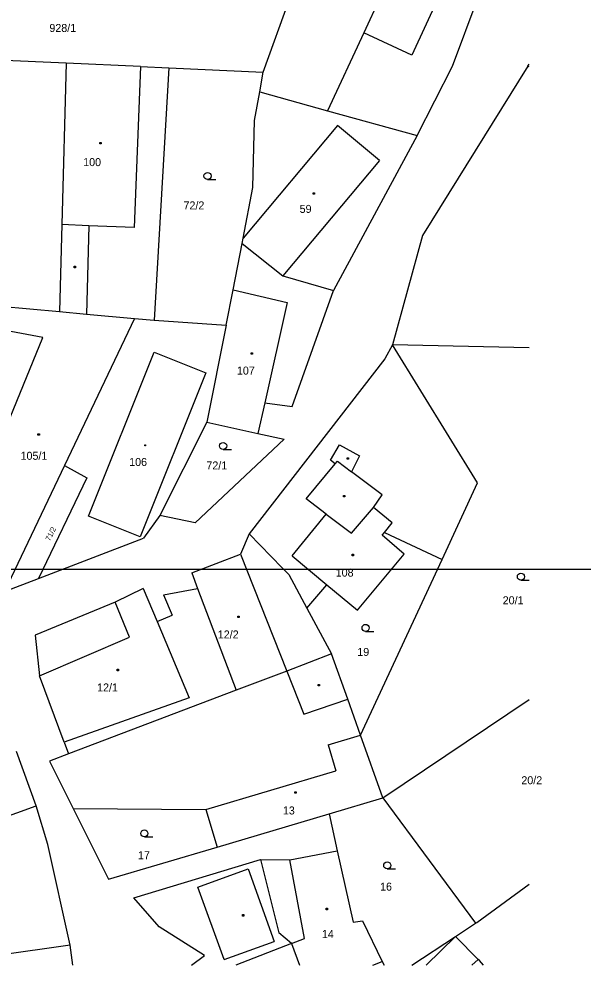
# Model space of a CAD drawing. Extents: x -770973 to -770265, y -1049936 to -1049427.
# Drawn here: x -770484.2 to -770424.3, y -1049934.8 to -1049834.2 of the extents above; entities that cross this region are included whole.
import ezdxf

# ---------------------------------------------------------------- set-up
doc = ezdxf.new("R2010")
doc.units = 0
for name, color, linetype in [('Vrstva 1', 7, 'Continuous'), ('Vrstva 14', 7, 'Continuous'), ('Vrstva 15', 7, 'Continuous'), ('Vrstva 2', 7, 'Continuous'), ('Vrstva 23', 7, 'Continuous'), ('Vrstva 25', 7, 'Continuous'), ('Vrstva 63', 7, 'Continuous')]:
    doc.layers.add(name, color=color, linetype=linetype)

msp = doc.modelspace()

# ---------------------------------------------------------------- linework, layer by layer
at = {"layer": 'Vrstva 1'}
for p, q in [((-770458.29, -1049839.9), (-770450.36, -1049817.83)), ((-770440.9, -1049821.18), (-770447.63, -1049835.71)), ((-770438.2, -1049839.27), (-770432.93, -1049825.06)), ((-770447.63, -1049835.71), (-770451.47, -1049843.99)), ((-770479.2, -1049838.96), (-770486.82, -1049838.62)), ((-770479.2, -1049838.96), (-770479.66, -1049856.1)), ((-770471.31, -1049839.31), (-770479.2, -1049838.96)), ((-770471.31, -1049839.31), (-770468.31, -1049839.45)), ((-770468.31, -1049839.45), (-770469.89, -1049866.23)), ((-770468.31, -1049839.45), (-770458.29, -1049839.9)), ((-770441.96, -1049846.64), (-770438.2, -1049839.27)), ((-770430.2, -1049839.26), (-770441.38, -1049857.25)), ((-770430.2, -1049839.26), (-770430.07, -1049839.05)), ((-770430.07, -1049839.34), (-770430.2, -1049839.26)), ((-770458.67, -1049841.99), (-770458.29, -1049839.9)), ((-770459.23, -1049845.04), (-770458.67, -1049841.99)), ((-770458.67, -1049841.99), (-770451.47, -1049843.99)), ((-770451.47, -1049843.99), (-770441.96, -1049846.64)), ((-770459.41, -1049852.14), (-770459.23, -1049845.04)), ((-770441.96, -1049846.64), (-770450.83, -1049863.11)), ((-770460.43, -1049857.53), (-770459.41, -1049852.14)), ((-770479.66, -1049856.1), (-770479.91, -1049865.34)), ((-770460.54, -1049858.09), (-770460.43, -1049857.53)), ((-770441.38, -1049857.25), (-770444.57, -1049868.85)), ((-770461.5, -1049863.01), (-770460.54, -1049858.09)), ((-770460.54, -1049858.09), (-770456.2, -1049861.52)), ((-770456.2, -1049861.52), (-770450.83, -1049863.11)), ((-770462.24, -1049866.78), (-770461.5, -1049863.01)), ((-770455.22, -1049875.43), (-770450.83, -1049863.11)), ((-770486.23, -1049864.75), (-770479.91, -1049865.34)), ((-770479.91, -1049865.34), (-770477.06, -1049865.61)), ((-770471.98, -1049866.08), (-770479.4, -1049881.69)), ((-770477.06, -1049865.61), (-770471.98, -1049866.08)), ((-770471.98, -1049866.08), (-770469.89, -1049866.23)), ((-770469.89, -1049866.23), (-770462.24, -1049866.78)), ((-770462.24, -1049866.78), (-770464.3, -1049877.09)), ((-770444.57, -1049868.85), (-770445.39, -1049870.36)), ((-770435.53, -1049883.52), (-770444.57, -1049868.85)), ((-770430.07, -1049869.18), (-770444.57, -1049868.85)), ((-770445.39, -1049870.36), (-770459.79, -1049888.94)), ((-770458.13, -1049875.04), (-770458.86, -1049878.29)), ((-770458.13, -1049875.04), (-770455.22, -1049875.43)), ((-770464.3, -1049877.09), (-770469.28, -1049887)), ((-770464.3, -1049877.09), (-770458.86, -1049878.29)), ((-770458.86, -1049878.29), (-770456.08, -1049878.9)), ((-770456.08, -1049878.9), (-770465.52, -1049887.77)), ((-770479.4, -1049881.69), (-770485.77, -1049895.07)), ((-770479.4, -1049881.69), (-770477.03, -1049882.99)), ((-770477.03, -1049882.99), (-770482.17, -1049893.68)), ((-770439.31, -1049891.66), (-770435.53, -1049883.52)), ((-770469.28, -1049887), (-770471.02, -1049889.4)), ((-770465.52, -1049887.77), (-770469.28, -1049887)), ((-770482.17, -1049893.68), (-770471.02, -1049889.4)), ((-770459.79, -1049888.94), (-770460.71, -1049891.12)), ((-770456.27, -1049892.56), (-770459.79, -1049888.94)), ((-770445.66, -1049889.1), (-770445.42, -1049888.81)), ((-770443.32, -1049891.12), (-770445.66, -1049889.1)), ((-770445.42, -1049888.81), (-770439.31, -1049891.66)), ((-770465.89, -1049893.1), (-770460.71, -1049891.12)), ((-770448.3, -1049897.07), (-770443.32, -1049891.12)), ((-770447.98, -1049910.33), (-770439.31, -1049891.66)), ((-770455.58, -1049893.28), (-770456.27, -1049892.56)), ((-770485.77, -1049895.07), (-770482.17, -1049893.68)), ((-770465.89, -1049893.1), (-770465.26, -1049894.75)), ((-770455.58, -1049893.28), (-770453.65, -1049896.86)), ((-770471.04, -1049894.75), (-770474.02, -1049896.22)), ((-770471.04, -1049894.75), (-770469.57, -1049898.26)), ((-770468.88, -1049895.42), (-770465.26, -1049894.75)), ((-770465.26, -1049894.75), (-770461.16, -1049905.56)), ((-770453.65, -1049896.86), (-770451.55, -1049894.35)), ((-770451.55, -1049894.35), (-770448.3, -1049897.07)), ((-770468.88, -1049895.42), (-770467.97, -1049897.59)), ((-770474.02, -1049896.22), (-770482.51, -1049899.71)), ((-770469.57, -1049898.26), (-770467.97, -1049897.59)), ((-770453.65, -1049896.86), (-770451.03, -1049901.71)), ((-770482.51, -1049899.71), (-770482.06, -1049904.03)), ((-770451.03, -1049901.71), (-770455.79, -1049903.52)), ((-770449.33, -1049906.52), (-770451.03, -1049901.71)), ((-770455.79, -1049903.52), (-770461.16, -1049905.56)), ((-770479.44, -1049911.09), (-770482.06, -1049904.03)), ((-770461.16, -1049905.56), (-770478.98, -1049912.33)), ((-770447.98, -1049910.33), (-770449.33, -1049906.52)), ((-770445.61, -1049917.01), (-770430.07, -1049906.54)), ((-770445.61, -1049917.01), (-770447.98, -1049910.33)), ((-770479.44, -1049911.09), (-770478.98, -1049912.33)), ((-770482.41, -1049917.84), (-770484.49, -1049912.07)), ((-770478.98, -1049912.33), (-770480.99, -1049913.1)), ((-770480.99, -1049913.1), (-770478.47, -1049918.14)), ((-770481.17, -1049921.95), (-770482.41, -1049917.84)), ((-770451.31, -1049918.7), (-770445.61, -1049917.01)), ((-770445.61, -1049917.01), (-770435.75, -1049930.32)), ((-770478.47, -1049918.14), (-770464.38, -1049918.23)), ((-770478.47, -1049918.14), (-770474.71, -1049925.65)), ((-770464.38, -1049918.23), (-770463.19, -1049922.23)), ((-770463.19, -1049922.23), (-770451.31, -1049918.7)), ((-770451.31, -1049918.7), (-770450.43, -1049922.62)), ((-770478.8, -1049932.64), (-770481.17, -1049921.95)), ((-770474.71, -1049925.65), (-770463.19, -1049922.23)), ((-770455.48, -1049923.57), (-770450.43, -1049922.62)), ((-770450.43, -1049922.62), (-770448.75, -1049930.19)), ((-770472.03, -1049927.6), (-770458.57, -1049923.56)), ((-770458.57, -1049923.56), (-770455.48, -1049923.57)), ((-770458.57, -1049923.56), (-770456.64, -1049931.32)), ((-770435.6, -1049930.22), (-770430.07, -1049926.18)), ((-770469.35, -1049930.71), (-770472.03, -1049927.6)), ((-770464.53, -1049933.76), (-770469.35, -1049930.71)), ((-770448.75, -1049930.19), (-770447.75, -1049930.05)), ((-770447.75, -1049930.05), (-770445.66, -1049934.37)), ((-770437.87, -1049931.71), (-770435.75, -1049930.32)), ((-770435.75, -1049930.32), (-770435.6, -1049930.22)), ((-770455.31, -1049932.48), (-770456.64, -1049931.32)), ((-770442.51, -1049934.76), (-770437.87, -1049931.71)), ((-770435.47, -1049934.16), (-770437.87, -1049931.71)), ((-770478.5, -1049934.76), (-770478.8, -1049932.64)), ((-770455.31, -1049932.48), (-770454.43, -1049934.76)), ((-770465.91, -1049934.76), (-770464.53, -1049933.76)), ((-770446.66, -1049934.76), (-770445.66, -1049934.37)), ((-770445.66, -1049934.37), (-770445.47, -1049934.76)), ((-770435.34, -1049934.29), (-770435.47, -1049934.16)), ((-770434.92, -1049934.76), (-770435.34, -1049934.29))]:
    msp.add_line(p, q, dxfattribs=at)
at = {"layer": 'Vrstva 2'}
for p, q in [((-770435.83, -1049823.65), (-770442.52, -1049838.08)), ((-770442.52, -1049838.08), (-770447.63, -1049835.71)), ((-770471.31, -1049839.31), (-770472.01, -1049856.39)), ((-770450.41, -1049845.55), (-770460.43, -1049857.53)), ((-770445.96, -1049849.28), (-770450.41, -1049845.55)), ((-770445.96, -1049849.28), (-770456.2, -1049861.52)), ((-770476.8, -1049856.21), (-770479.66, -1049856.1)), ((-770476.8, -1049856.21), (-770477.06, -1049865.61)), ((-770472.01, -1049856.39), (-770476.8, -1049856.21)), ((-770461.5, -1049863.01), (-770455.74, -1049864.37)), ((-770455.74, -1049864.37), (-770458.13, -1049875.04)), ((-770481.71, -1049868.08), (-770486.23, -1049867.24)), ((-770491.74, -1049892.63), (-770481.71, -1049868.08)), ((-770476.85, -1049887.07), (-770469.89, -1049869.65)), ((-770469.89, -1049869.65), (-770464.4, -1049871.84)), ((-770464.4, -1049871.84), (-770471.36, -1049889.26)), ((-770451.15, -1049881.13), (-770450.2, -1049879.48)), ((-770450.2, -1049879.48), (-770448.07, -1049880.67)), ((-770448.07, -1049880.67), (-770448.92, -1049882.36)), ((-770453.75, -1049885.24), (-770450.65, -1049881.51)), ((-770450.65, -1049881.51), (-770451.15, -1049881.13)), ((-770450.65, -1049881.51), (-770450.42, -1049881.23)), ((-770450.42, -1049881.23), (-770448.92, -1049882.36)), ((-770445.66, -1049884.8), (-770448.92, -1049882.36)), ((-770451.61, -1049886.86), (-770453.75, -1049885.24)), ((-770446.6, -1049886.14), (-770445.66, -1049884.8)), ((-770448.94, -1049888.89), (-770446.6, -1049886.14)), ((-770444.59, -1049887.79), (-770446.6, -1049886.14)), ((-770471.36, -1049889.26), (-770476.85, -1049887.07)), ((-770455.22, -1049891.28), (-770451.61, -1049886.86)), ((-770451.61, -1049886.86), (-770448.94, -1049888.89)), ((-770445.42, -1049888.81), (-770444.59, -1049887.79)), ((-770460.71, -1049891.12), (-770455.79, -1049903.52)), ((-770455.22, -1049891.28), (-770451.55, -1049894.35)), ((-770472.48, -1049899.92), (-770474.02, -1049896.22)), ((-770469.57, -1049898.26), (-770466.17, -1049906.37)), ((-770482.06, -1049904.03), (-770472.48, -1049899.92)), ((-770455.79, -1049903.52), (-770453.97, -1049908.11)), ((-770466.17, -1049906.37), (-770479.44, -1049911.09)), ((-770453.97, -1049908.11), (-770449.33, -1049906.52)), ((-770451.41, -1049911.35), (-770447.98, -1049910.33)), ((-770451.41, -1049911.35), (-770450.59, -1049914.13)), ((-770464.38, -1049918.23), (-770450.59, -1049914.13)), ((-770504.38, -1049925.82), (-770482.41, -1049917.84)), ((-770453.91, -1049931.94), (-770455.48, -1049923.57)), ((-770465.23, -1049926.47), (-770459.9, -1049924.55)), ((-770459.9, -1049924.55), (-770457.13, -1049932.25)), ((-770462.46, -1049934.17), (-770465.23, -1049926.47)), ((-770455.31, -1049932.48), (-770453.91, -1049931.94)), ((-770437.87, -1049931.71), (-770440.98, -1049934.76)), ((-770478.8, -1049932.64), (-770493.71, -1049934.76)), ((-770462.46, -1049934.17), (-770457.13, -1049932.25)), ((-770455.31, -1049932.48), (-770461.22, -1049934.76)), ((-770435.47, -1049934.16), (-770436.14, -1049934.76))]:
    msp.add_line(p, q, dxfattribs=at)
at = {"layer": 'Vrstva 23'}
for p, q in [((-770464.21, -1049851.3), (-770463.33, -1049851.3)), ((-770462.55, -1049879.99), (-770461.67, -1049879.99)), ((-770430.94, -1049893.88), (-770430.06, -1049893.88)), ((-770447.43, -1049899.31), (-770446.55, -1049899.31)), ((-770470.91, -1049921.15), (-770470.03, -1049921.15)), ((-770445.13, -1049924.54), (-770444.25, -1049924.54))]:
    msp.add_line(p, q, dxfattribs=at)
for centre in [(-770464.21, -1049850.93), (-770462.55, -1049879.61), (-770430.94, -1049893.5), (-770447.43, -1049898.94), (-770470.91, -1049920.77), (-770445.13, -1049924.17)]:
    msp.add_circle(centre, 0.375, dxfattribs=at)
at = {"layer": 'Vrstva 25'}
for p, q in [((-770475.64, -1049847.38), (-770475.49, -1049847.38)), ((-770475.64, -1049847.53), (-770475.64, -1049847.38)), ((-770475.49, -1049847.38), (-770475.49, -1049847.53)), ((-770475.49, -1049847.53), (-770475.64, -1049847.53)), ((-770452.99, -1049852.72), (-770452.84, -1049852.72)), ((-770452.99, -1049852.87), (-770452.99, -1049852.72)), ((-770452.84, -1049852.87), (-770452.99, -1049852.87)), ((-770452.84, -1049852.72), (-770452.84, -1049852.87)), ((-770478.36, -1049860.52), (-770478.21, -1049860.52)), ((-770478.36, -1049860.67), (-770478.36, -1049860.52)), ((-770478.21, -1049860.52), (-770478.21, -1049860.67)), ((-770478.21, -1049860.67), (-770478.36, -1049860.67)), ((-770459.57, -1049869.7), (-770459.42, -1049869.7)), ((-770459.57, -1049869.85), (-770459.57, -1049869.7)), ((-770459.42, -1049869.85), (-770459.57, -1049869.85)), ((-770459.42, -1049869.7), (-770459.42, -1049869.85)), ((-770482.21, -1049878.31), (-770482.06, -1049878.31)), ((-770482.21, -1049878.46), (-770482.21, -1049878.31)), ((-770482.06, -1049878.46), (-770482.21, -1049878.46)), ((-770482.06, -1049878.31), (-770482.06, -1049878.46)), ((-770470.88, -1049879.49), (-770470.78, -1049879.49)), ((-770470.88, -1049879.59), (-770470.88, -1049879.49)), ((-770470.78, -1049879.59), (-770470.88, -1049879.59)), ((-770470.78, -1049879.49), (-770470.78, -1049879.59)), ((-770449.4, -1049880.86), (-770449.25, -1049880.86)), ((-770449.4, -1049881.01), (-770449.4, -1049880.86)), ((-770449.25, -1049881.01), (-770449.4, -1049881.01)), ((-770449.25, -1049880.86), (-770449.25, -1049881.01)), ((-770449.78, -1049884.88), (-770449.63, -1049884.88)), ((-770449.78, -1049885.03), (-770449.78, -1049884.88)), ((-770449.63, -1049885.03), (-770449.78, -1049885.03)), ((-770449.63, -1049884.88), (-770449.63, -1049885.03)), ((-770448.87, -1049891.12), (-770448.72, -1049891.12)), ((-770448.87, -1049891.27), (-770448.87, -1049891.12)), ((-770448.72, -1049891.27), (-770448.87, -1049891.27)), ((-770448.72, -1049891.12), (-770448.72, -1049891.27)), ((-770461, -1049897.7), (-770460.85, -1049897.7)), ((-770461, -1049897.85), (-770461, -1049897.7)), ((-770460.85, -1049897.7), (-770460.85, -1049897.85)), ((-770460.85, -1049897.85), (-770461, -1049897.85)), ((-770473.82, -1049903.34), (-770473.67, -1049903.34)), ((-770473.82, -1049903.49), (-770473.82, -1049903.34)), ((-770473.67, -1049903.49), (-770473.82, -1049903.49)), ((-770473.67, -1049903.34), (-770473.67, -1049903.49)), ((-770452.46, -1049904.95), (-770452.31, -1049904.95)), ((-770452.46, -1049905.1), (-770452.46, -1049904.95)), ((-770452.31, -1049905.1), (-770452.46, -1049905.1)), ((-770452.31, -1049904.95), (-770452.31, -1049905.1)), ((-770454.95, -1049916.35), (-770454.8, -1049916.35)), ((-770454.95, -1049916.5), (-770454.95, -1049916.35)), ((-770454.8, -1049916.5), (-770454.95, -1049916.5)), ((-770454.8, -1049916.35), (-770454.8, -1049916.5)), ((-770451.62, -1049928.73), (-770451.47, -1049928.73)), ((-770451.62, -1049928.88), (-770451.62, -1049928.73)), ((-770451.47, -1049928.88), (-770451.62, -1049928.88)), ((-770451.47, -1049928.73), (-770451.47, -1049928.88)), ((-770460.49, -1049929.4), (-770460.34, -1049929.4)), ((-770460.49, -1049929.55), (-770460.49, -1049929.4)), ((-770460.34, -1049929.55), (-770460.49, -1049929.55)), ((-770460.34, -1049929.4), (-770460.34, -1049929.55))]:
    msp.add_line(p, q, dxfattribs=at)
at = {"layer": 'Vrstva 63'}
msp.add_lwpolyline([(-770858.67, -1049892.7), (-770264.67, -1049892.7), (-770264.67, -1049472.7), (-770858.67, -1049472.7), (-770858.67, -1049892.7)], dxfattribs=at)

# ---------------------------------------------------------------- texts
at = {"layer": 'Vrstva 14'}
for s, p in [('928/1', (-770481, -1049835.63)), ('72/2', (-770466.76, -1049854.48)), ('72/1', (-770464.33, -1049882.11)), ('20/1', (-770432.87, -1049896.43)), ('19', (-770448.31, -1049901.92)), ('20/2', (-770430.89, -1049915.55)), ('17', (-770471.59, -1049923.51)), ('16', (-770445.89, -1049926.85))]:
    msp.add_text(s, height=0.85, dxfattribs=at).set_placement(p)
msp.add_text('71/2', height=0.57, rotation=63.1342, dxfattribs=at).set_placement((-770480.95, -1049889.76))
at = {"layer": 'Vrstva 15'}
for s, p in [('100', (-770477.41, -1049849.88)), ('59', (-770454.43, -1049854.85)), ('107', (-770461.09, -1049872.03)), ('105/1', (-770484.06, -1049881.08)), ('106', (-770472.53, -1049881.74)), ('108', (-770450.6, -1049893.49)), ('12/2', (-770463.12, -1049900.06)), ('12/1', (-770475.93, -1049905.69)), ('13', (-770456.21, -1049918.76)), ('14', (-770452.07, -1049931.89))]:
    msp.add_text(s, height=0.85, dxfattribs=at).set_placement(p)

doc.saveas('drawing.dxf')
